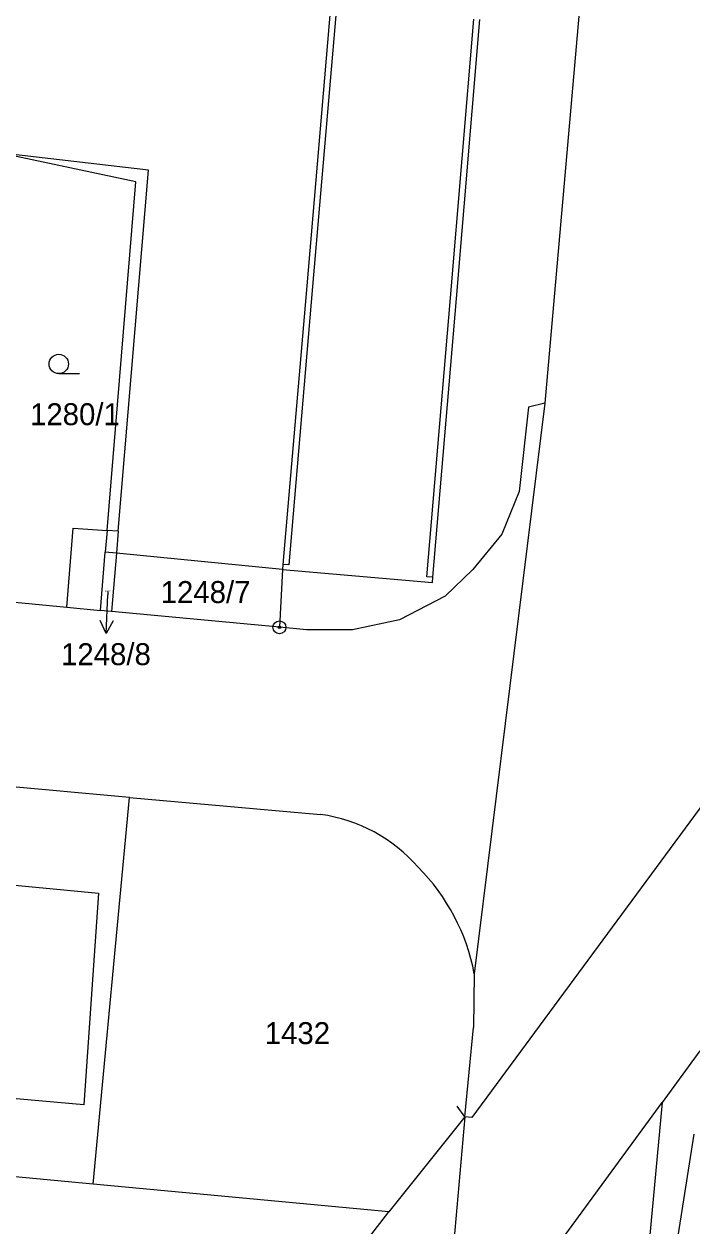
# Model space of a CAD drawing. Extents: x -755819 to -753140, y -1169796 to -1166000.
# Drawn here: x -755492 to -755440.3, y -1167320.5 to -1167227.4 of the extents above; entities that cross this region are included whole.
import ezdxf

# ---------------------------------------------------------------- set-up
doc = ezdxf.new("R2010")
doc.units = 0
for name, color, linetype in [('Vrstva 1', 7, 'Continuous'), ('Vrstva 16', 7, 'Continuous'), ('Vrstva 18', 7, 'Continuous'), ('Vrstva 24', 7, 'Continuous'), ('Vrstva 25', 7, 'Continuous'), ('Vrstva 26', 7, 'Continuous'), ('Vrstva 4', 7, 'Continuous')]:
    doc.layers.add(name, color=color, linetype=linetype)

msp = doc.modelspace()

# ---------------------------------------------------------------- linework, layer by layer
at = {"layer": 'Vrstva 1'}
for p, q in [((-755468.3, -1167226.11), (-755470.14, -1167247.69)), ((-755458.55, -1167248.67), (-755456.73, -1167227.07)), ((-755449.06, -1167226.82), (-755451.7, -1167256.77)), ((-755483.37, -1167239.63), (-755493.98, -1167237.39)), ((-755485.59, -1167266.63), (-755483.37, -1167239.63)), ((-755470.14, -1167247.69), (-755471.98, -1167269.26)), ((-755460.37, -1167270.25), (-755458.55, -1167248.67)), ((-755451.7, -1167256.77), (-755457.17, -1167300.95)), ((-755452.97, -1167257.08), (-755453.68, -1167263.61)), ((-755451.7, -1167256.77), (-755452.97, -1167257.08)), ((-755453.68, -1167263.61), (-755455.03, -1167266.93)), ((-755485.59, -1167266.63), (-755485.73, -1167268.32)), ((-755455.03, -1167266.93), (-755457.27, -1167269.64)), ((-755486.1, -1167272.82), (-755485.73, -1167268.32)), ((-755484.87, -1167268.4), (-755485.73, -1167268.32)), ((-755484.87, -1167268.4), (-755485.25, -1167272.9)), ((-755472.02, -1167269.66), (-755484.87, -1167268.4)), ((-755471.98, -1167269.26), (-755472.02, -1167269.66)), ((-755472.02, -1167269.66), (-755472.25, -1167274.13)), ((-755472.02, -1167269.66), (-755460.4, -1167270.65)), ((-755457.27, -1167269.64), (-755459.43, -1167271.71)), ((-755505.81, -1167270.94), (-755488.72, -1167272.57)), ((-755460.4, -1167270.65), (-755460.37, -1167270.25)), ((-755459.43, -1167271.71), (-755462.95, -1167273.54)), ((-755488.72, -1167272.57), (-755486.1, -1167272.82)), ((-755485.25, -1167272.9), (-755486.1, -1167272.82)), ((-755472.25, -1167274.13), (-755485.25, -1167272.9)), ((-755462.95, -1167273.54), (-755466.6, -1167274.33)), ((-755470.16, -1167274.33), (-755472.25, -1167274.13)), ((-755466.6, -1167274.33), (-755470.16, -1167274.33)), ((-755483.86, -1167287.31), (-755502.64, -1167285.61)), ((-755437.51, -1167285.15), (-755457.35, -1167312.07)), ((-755486.66, -1167317.24), (-755483.86, -1167287.31)), ((-755483.86, -1167287.31), (-755469.06, -1167288.62)), ((-755495.87, -1167293.8), (-755486.26, -1167294.72)), ((-755486.26, -1167294.72), (-755487.4, -1167311.1)), ((-755457.17, -1167300.95), (-755457.22, -1167305.11)), ((-755457.89, -1167312.02), (-755457.22, -1167305.11)), ((-755439.71, -1167306.92), (-755442.63, -1167310.91)), ((-755487.4, -1167311.1), (-755497.29, -1167310.24)), ((-755459.27, -1167333.69), (-755442.63, -1167310.91)), ((-755442.63, -1167310.91), (-755444.91, -1167335.73)), ((-755457.89, -1167312.02), (-755463.78, -1167319.39)), ((-755457.35, -1167312.07), (-755457.89, -1167312.02)), ((-755486.66, -1167317.24), (-755527, -1167313.51)), ((-755440.18, -1167313.38), (-755442.75, -1167329.72)), ((-755463.78, -1167319.39), (-755486.66, -1167317.24)), ((-755474.62, -1167333.33), (-755463.78, -1167319.39))]:
    msp.add_line(p, q, dxfattribs=at)
for centre, radius, start, end in [((-755470.715, -1167300.685), 12.178, 40.97194, 82.19118), ((-755472.667, -1167303.85), 15.766, 10.59752, 45.0054)]:
    msp.add_arc(centre, radius, start, end, dxfattribs=at)
at = {"layer": 'Vrstva 16'}
for p in [(-755485.659, -1167274.608), (-755485.53, -1167271.36)]:
    msp.add_line(p, (-755485.54, -1167271.61), dxfattribs=at)
msp.add_lwpolyline([(-755485.12, -1167273.628), (-755485.659, -1167274.608), (-755486.119, -1167273.589)], dxfattribs=at)
at = {"layer": 'Vrstva 24'}
for radius in [0.5, 0.1]:
    msp.add_circle((-755472.25, -1167274.13), radius, dxfattribs=at)
at = {"layer": 'Vrstva 25'}
msp.add_line((-755489.33, -1167254.49), (-755487.73, -1167254.49), dxfattribs=at)
msp.add_circle((-755489.33, -1167253.74), 0.75, dxfattribs=at)
at = {"layer": 'Vrstva 26'}
msp.add_line((-755457.89, -1167312.02), (-755458.48, -1167311.213), dxfattribs=at)
at = {"layer": 'Vrstva 4'}
for p, q in [((-755467.84, -1167226.15), (-755469.68, -1167247.73)), ((-755459.01, -1167248.63), (-755457.19, -1167227.03)), ((-755482.38, -1167238.73), (-755493.98, -1167237.39)), ((-755484.73, -1167266.69), (-755482.38, -1167238.73)), ((-755469.68, -1167247.73), (-755471.52, -1167269.3)), ((-755460.83, -1167270.21), (-755459.01, -1167248.63)), ((-755488.72, -1167272.57), (-755488.22, -1167266.44)), ((-755488.22, -1167266.44), (-755485.59, -1167266.63)), ((-755484.73, -1167266.69), (-755485.59, -1167266.63)), ((-755484.73, -1167266.69), (-755484.87, -1167268.4)), ((-755471.52, -1167269.3), (-755471.98, -1167269.26)), ((-755460.37, -1167270.25), (-755460.83, -1167270.21)), ((-755457.89, -1167312.02), (-755459.81, -1167333.64))]:
    msp.add_line(p, q, dxfattribs=at)

# ---------------------------------------------------------------- texts
at = {"layer": 'Vrstva 16'}
msp.add_text('1248/8', height=1.7, dxfattribs=at).set_placement((-755489.157, -1167277.06))
at = {"layer": 'Vrstva 18'}
for s, height, p in [('1280/1', 1.7, (-755491.557, -1167258.48)), ('1248/7', 1.7, (-755481.444, -1167272.25)), ('1248/8', 0.1, (-755485.759, -1167271.36)), ('1432', 1.7, (-755473.387, -1167306.4))]:
    msp.add_text(s, height=height, dxfattribs=at).set_placement(p)

doc.saveas('drawing.dxf')
